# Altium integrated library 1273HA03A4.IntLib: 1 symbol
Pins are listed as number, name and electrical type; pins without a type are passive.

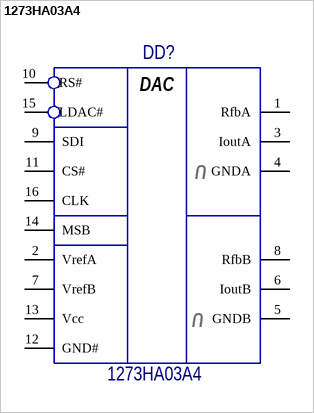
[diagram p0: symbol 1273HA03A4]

## 1273HA03A4
designator DD?
footprint 4112.16-3
pins: 1 RfbA, 2 VrefA, 3 IoutA, 4 GNDA, 5 GNDB, 6 IoutB, 7 VrefB, 8 RfbB, 9 SDI, 10 RS#, 11 CS#, 12 GND#, 13 Vcc, 14 MSB, 15 LDAC#, 16 CLK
